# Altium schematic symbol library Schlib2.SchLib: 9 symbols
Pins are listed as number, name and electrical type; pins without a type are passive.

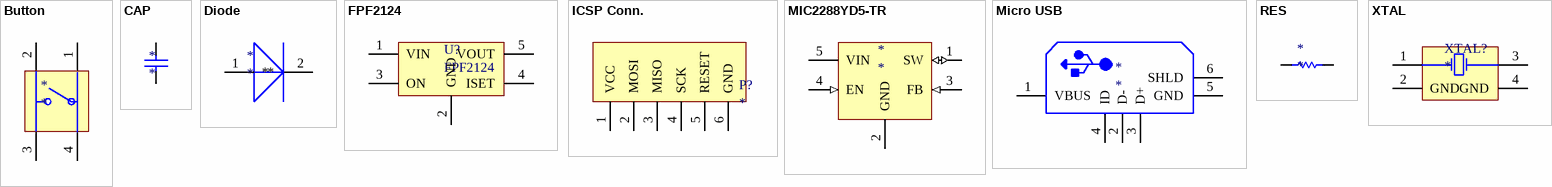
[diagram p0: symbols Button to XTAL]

## Button
designator *
pins: 1 A, 2 B, 3 B', 4 A'

## CAP
designator *
footprint CAP
pins: 1, 2

## Diode
designator *
pins: 1 *, 2 *

## FPF2124
designator U?
footprint SOT23-5
pins: 1 VIN, 2 GND, 3 ON, 4 ISET, 5 VOUT

## ICSP Conn.
designator P?
pins: 1 VCC, 2 MOSI, 3 MISO, 4 SCK, 5 RESET, 6 GND

## MIC2288YD5-TR
designator *
pins: 1 SW (io) "Boost converter input voltage", 2 GND (power) "Voltage feedback of adjustable version. Must be connected to VOUT at fixed output voltage versions.", 3 FB (in) "Control / logic and power ground", 4 EN (in) "Boost converter output voltage", 5 VIN (power) "Connection for Inductor"

## Micro USB
designator *
footprint Micro USB
pins: 1 VBUS, 2 D-, 3 D+, 4 ID, 5 GND, 6 SHLD

## RES
designator *
footprint RES
pins: 1, 2

## XTAL
designator XTAL?
pins: 1 X1, 2 GND (power), 3 X2, 4 GND (power)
